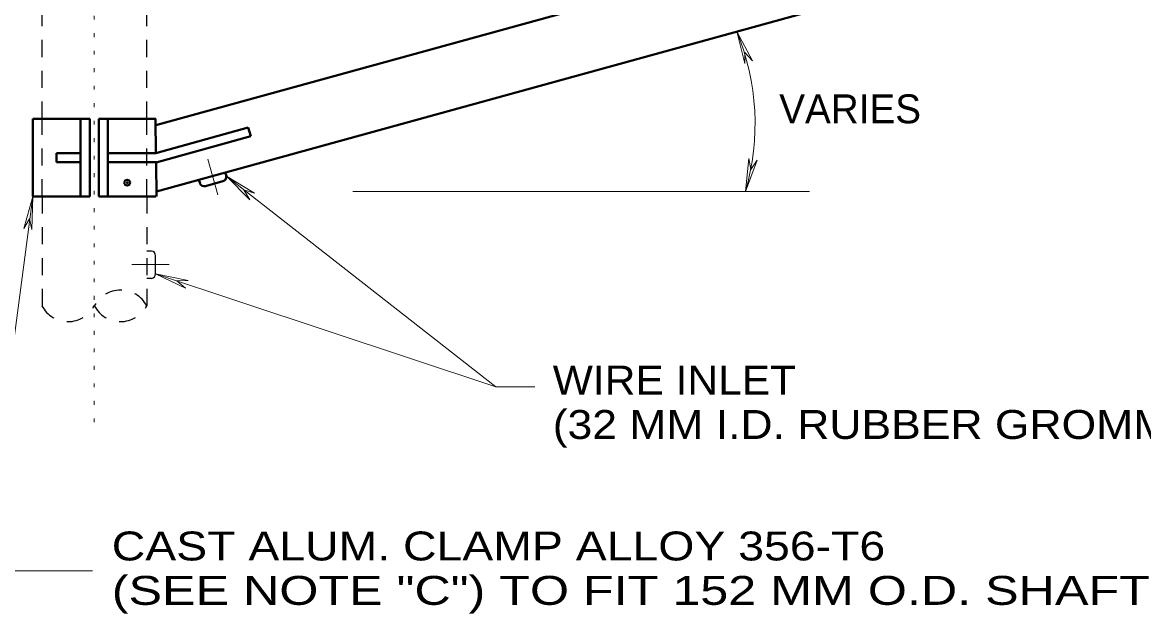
# Model space of a CAD drawing. Extents: x 312583 to 312854, y 144419 to 144597.
# Drawn here: x 312726.34 to 312755.82, y 144523.9 to 144539.43 of the extents above; entities that cross this region are included whole.
import ezdxf

# ---------------------------------------------------------------- set-up
doc = ezdxf.new("R2010")
doc.units = 0
doc.header["$LTSCALE"] = 0.3
doc.header["$PDMODE"] = 32
doc.header["$PDSIZE"] = 0.15
doc.linetypes.add('DOTTED', pattern=[1.5, 0.3, -1.2])
doc.linetypes.add('SHORT_DASHED', pattern=[2.7, 1.5, -1.2])
doc.layers.add('1', color=7, linetype='Continuous', lineweight=40)

msp = doc.modelspace()

# ---------------------------------------------------------------- linework, layer by layer
at = {"layer": '1', "linetype": 'DOTTED', "lineweight": 13}
msp.add_line((312728.2319, 144528.9275), (312728.2319, 144573.4478), dxfattribs=at)
at = {"layer": '1'}
for p, q in [((312729.8495, 144536.7322), (312829.0255, 144564.0332)), ((312729.8649, 144534.9918), (312829.4702, 144562.4155)), ((312726.6142, 144536.9008), (312728.1169, 144536.9008)), ((312726.6142, 144535.8812), (312726.6142, 144536.9008)), ((312727.8715, 144535.8812), (312727.8715, 144536.9008)), ((312728.1169, 144535.8812), (312728.1169, 144536.9008)), ((312729.8495, 144536.9008), (312728.3545, 144536.9008)), ((312728.3545, 144535.8812), (312728.3545, 144536.9008)), ((312728.5922, 144535.8812), (312728.5922, 144536.9008)), ((312729.8419, 144536.9008), (312729.8495, 144535.9962)), ((312729.8495, 144535.9962), (312732.2799, 144536.6708)), ((312729.8572, 144535.7508), (312732.3489, 144536.4408)), ((312732.2799, 144536.6708), (312732.3489, 144536.4408)), ((312726.6142, 144535.8812), (312726.6142, 144534.8615)), ((312727.2352, 144535.9962), (312727.2352, 144535.7585)), ((312727.8715, 144535.9962), (312727.2352, 144535.9962)), ((312727.8715, 144535.8812), (312727.8715, 144534.8615)), ((312728.1169, 144535.8812), (312728.1169, 144534.8615)), ((312728.3545, 144535.8812), (312728.3545, 144534.8615)), ((312729.8495, 144535.9962), (312728.5922, 144535.9962)), ((312728.5922, 144535.8812), (312728.5922, 144534.8615)), ((312727.8715, 144535.7585), (312727.2352, 144535.7585)), ((312729.8725, 144535.7585), (312728.5922, 144535.7585)), ((312729.8572, 144535.7508), (312729.8649, 144534.8615)), ((312731.0149, 144535.1988), (312730.9842, 144535.2985)), ((312731.1529, 144535.1298), (312731.6129, 144535.2602)), ((312731.7049, 144535.3905), (312731.6742, 144535.4902))]:
    msp.add_line(p, q, dxfattribs=at)
at = {"layer": '1', "linetype": 'SHORT_DASHED', "lineweight": 25}
for p, q in [((312726.8595, 144536.9008), (312726.8595, 144549.2365)), ((312729.6119, 144536.9008), (312729.6119, 144549.2365)), ((312726.8595, 144534.8615), (312726.8595, 144536.9008)), ((312729.6119, 144534.8615), (312729.6119, 144536.9008)), ((312726.8595, 144534.8615), (312726.8595, 144531.9865)), ((312729.6119, 144534.8615), (312729.6119, 144531.9865))]:
    msp.add_line(p, q, dxfattribs=at)
at = {"layer": '1', "lineweight": 13}
for p, q in [((312745.1215, 144539.1932), (312745.3362, 144538.3498)), ((312745.1215, 144539.1932), (312745.5355, 144538.4265)), ((312745.3362, 144538.3498), (312745.3362, 144538.6412)), ((312745.5355, 144538.4265), (312745.3362, 144538.6412)), ((312731.2219, 144535.8428), (312731.4825, 144534.8998)), ((312745.3515, 144534.9918), (312745.4435, 144535.8582)), ((312745.3515, 144534.9918), (312745.6582, 144535.8122)), ((312745.4435, 144535.8582), (312745.4895, 144535.5668)), ((312745.6582, 144535.8122), (312745.4895, 144535.5668)), ((312731.7049, 144535.3905), (312732.3182, 144534.7695)), ((312731.7049, 144535.3905), (312732.4485, 144534.9458)), ((312732.3182, 144534.7695), (312732.1649, 144535.0302)), ((312732.4485, 144534.9458), (312732.1649, 144535.0302)), ((312735.0322, 144534.9918), (312747.0382, 144534.9918)), ((312726.6142, 144534.8615), (312726.3796, 144534.0193)), ((312726.6142, 144534.8615), (312726.5884, 144533.9896)), ((312726.3796, 144534.0193), (312726.5253, 144534.2741)), ((312726.5884, 144533.9896), (312726.5253, 144534.2741)), ((312729.2209, 144533.0675), (312730.2022, 144533.0752)), ((312729.8419, 144532.8222), (312730.6315, 144532.4542)), ((312729.8419, 144532.8222), (312730.7005, 144532.6535)), ((312730.7005, 144532.6535), (312730.4015, 144532.6382)), ((312730.6315, 144532.4542), (312730.4015, 144532.6382)), ((312738.7889, 144529.8552), (312739.8171, 144529.8552))]:
    msp.add_line(p, q, dxfattribs=at)
at = {"layer": '1', "lineweight": 25}
for p, q in [((312729.7345, 144533.4202), (312729.6119, 144533.4202)), ((312729.8419, 144532.8222), (312729.8419, 144533.3052)), ((312729.7345, 144532.7072), (312729.6119, 144532.7072))]:
    msp.add_line(p, q, dxfattribs=at)
at = {"layer": '1', "lineweight": 13}
for points in [[(312729.8419, 144532.8222), (312738.7889, 144529.8552), (312731.7049, 144535.3905)], [(312726.6142, 144534.8615), (312725.3075, 144525.0233), (312728.1825, 144525.0233)]]:
    msp.add_lwpolyline(points, dxfattribs=at)
at = {"layer": '1'}
for points in [[(312726.6142, 144534.8615), (312727.8715, 144534.8615), (312728.1169, 144534.8615)], [(312729.8495, 144534.8615), (312728.5922, 144534.8615), (312728.3545, 144534.8615)]]:
    msp.add_lwpolyline(points, dxfattribs=at)
at = {"layer": '1', "lineweight": 13}
msp.add_arc((312739.2922, 144536.7697), 6.3128, 343.65192, 22.57618, dxfattribs=at)
at = {"layer": '1'}
for centre, start, end in [((312731.5842, 144535.3734), 285.1627, 8.24485), ((312731.1213, 144535.2458), 202.50814, 285.66313)]:
    msp.add_arc(centre, 0.1193, start, end, dxfattribs=at)
at = {"layer": '1', "lineweight": 25}
for centre, start, end in [((312729.7219, 144533.305), 359.7352, 82.81735), ((312729.7217, 144532.8248), 277.08064, 0.23563)]:
    msp.add_arc(centre, 0.1193, start, end, dxfattribs=at)
at = {"layer": '1', "linetype": 'SHORT_DASHED', "lineweight": 25}
for centre, start, end in [((312728.9226, 144531.6203), 27.93563, 152.06437), ((312727.545, 144532.3508), 207.93563, 332.06437), ((312728.9226, 144532.3508), 207.93563, 332.06437)]:
    msp.add_arc(centre, 0.7796, start, end, dxfattribs=at)
at = {"layer": '1'}
msp.add_point((312729.0982, 144535.2218), dxfattribs=at)

# ---------------------------------------------------------------- texts
msp.add_text('VARIES', height=0.76, dxfattribs=at).set_placement((312746.2392, 144536.781))
for s, width, p in [('WIRE INLET', 1.1, (312740.285, 144529.6548)), ('(32 MM I.D. RUBBER GROMMET)', 1.15, (312740.285, 144528.4885)), ('CAST ALUM. CLAMP ALLOY 356-T6', 1.2, (312728.6923, 144525.2964)), ('(SEE NOTE "C") TO FIT 152 MM O.D. SHAFT "T" & "C"', 1.3, (312728.6923, 144524.1301))]:
    msp.add_text(s, height=0.76, dxfattribs=dict(at, width=width)).set_placement(p)

doc.saveas('drawing.dxf')
